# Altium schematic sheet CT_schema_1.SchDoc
size 327 x 469 mm
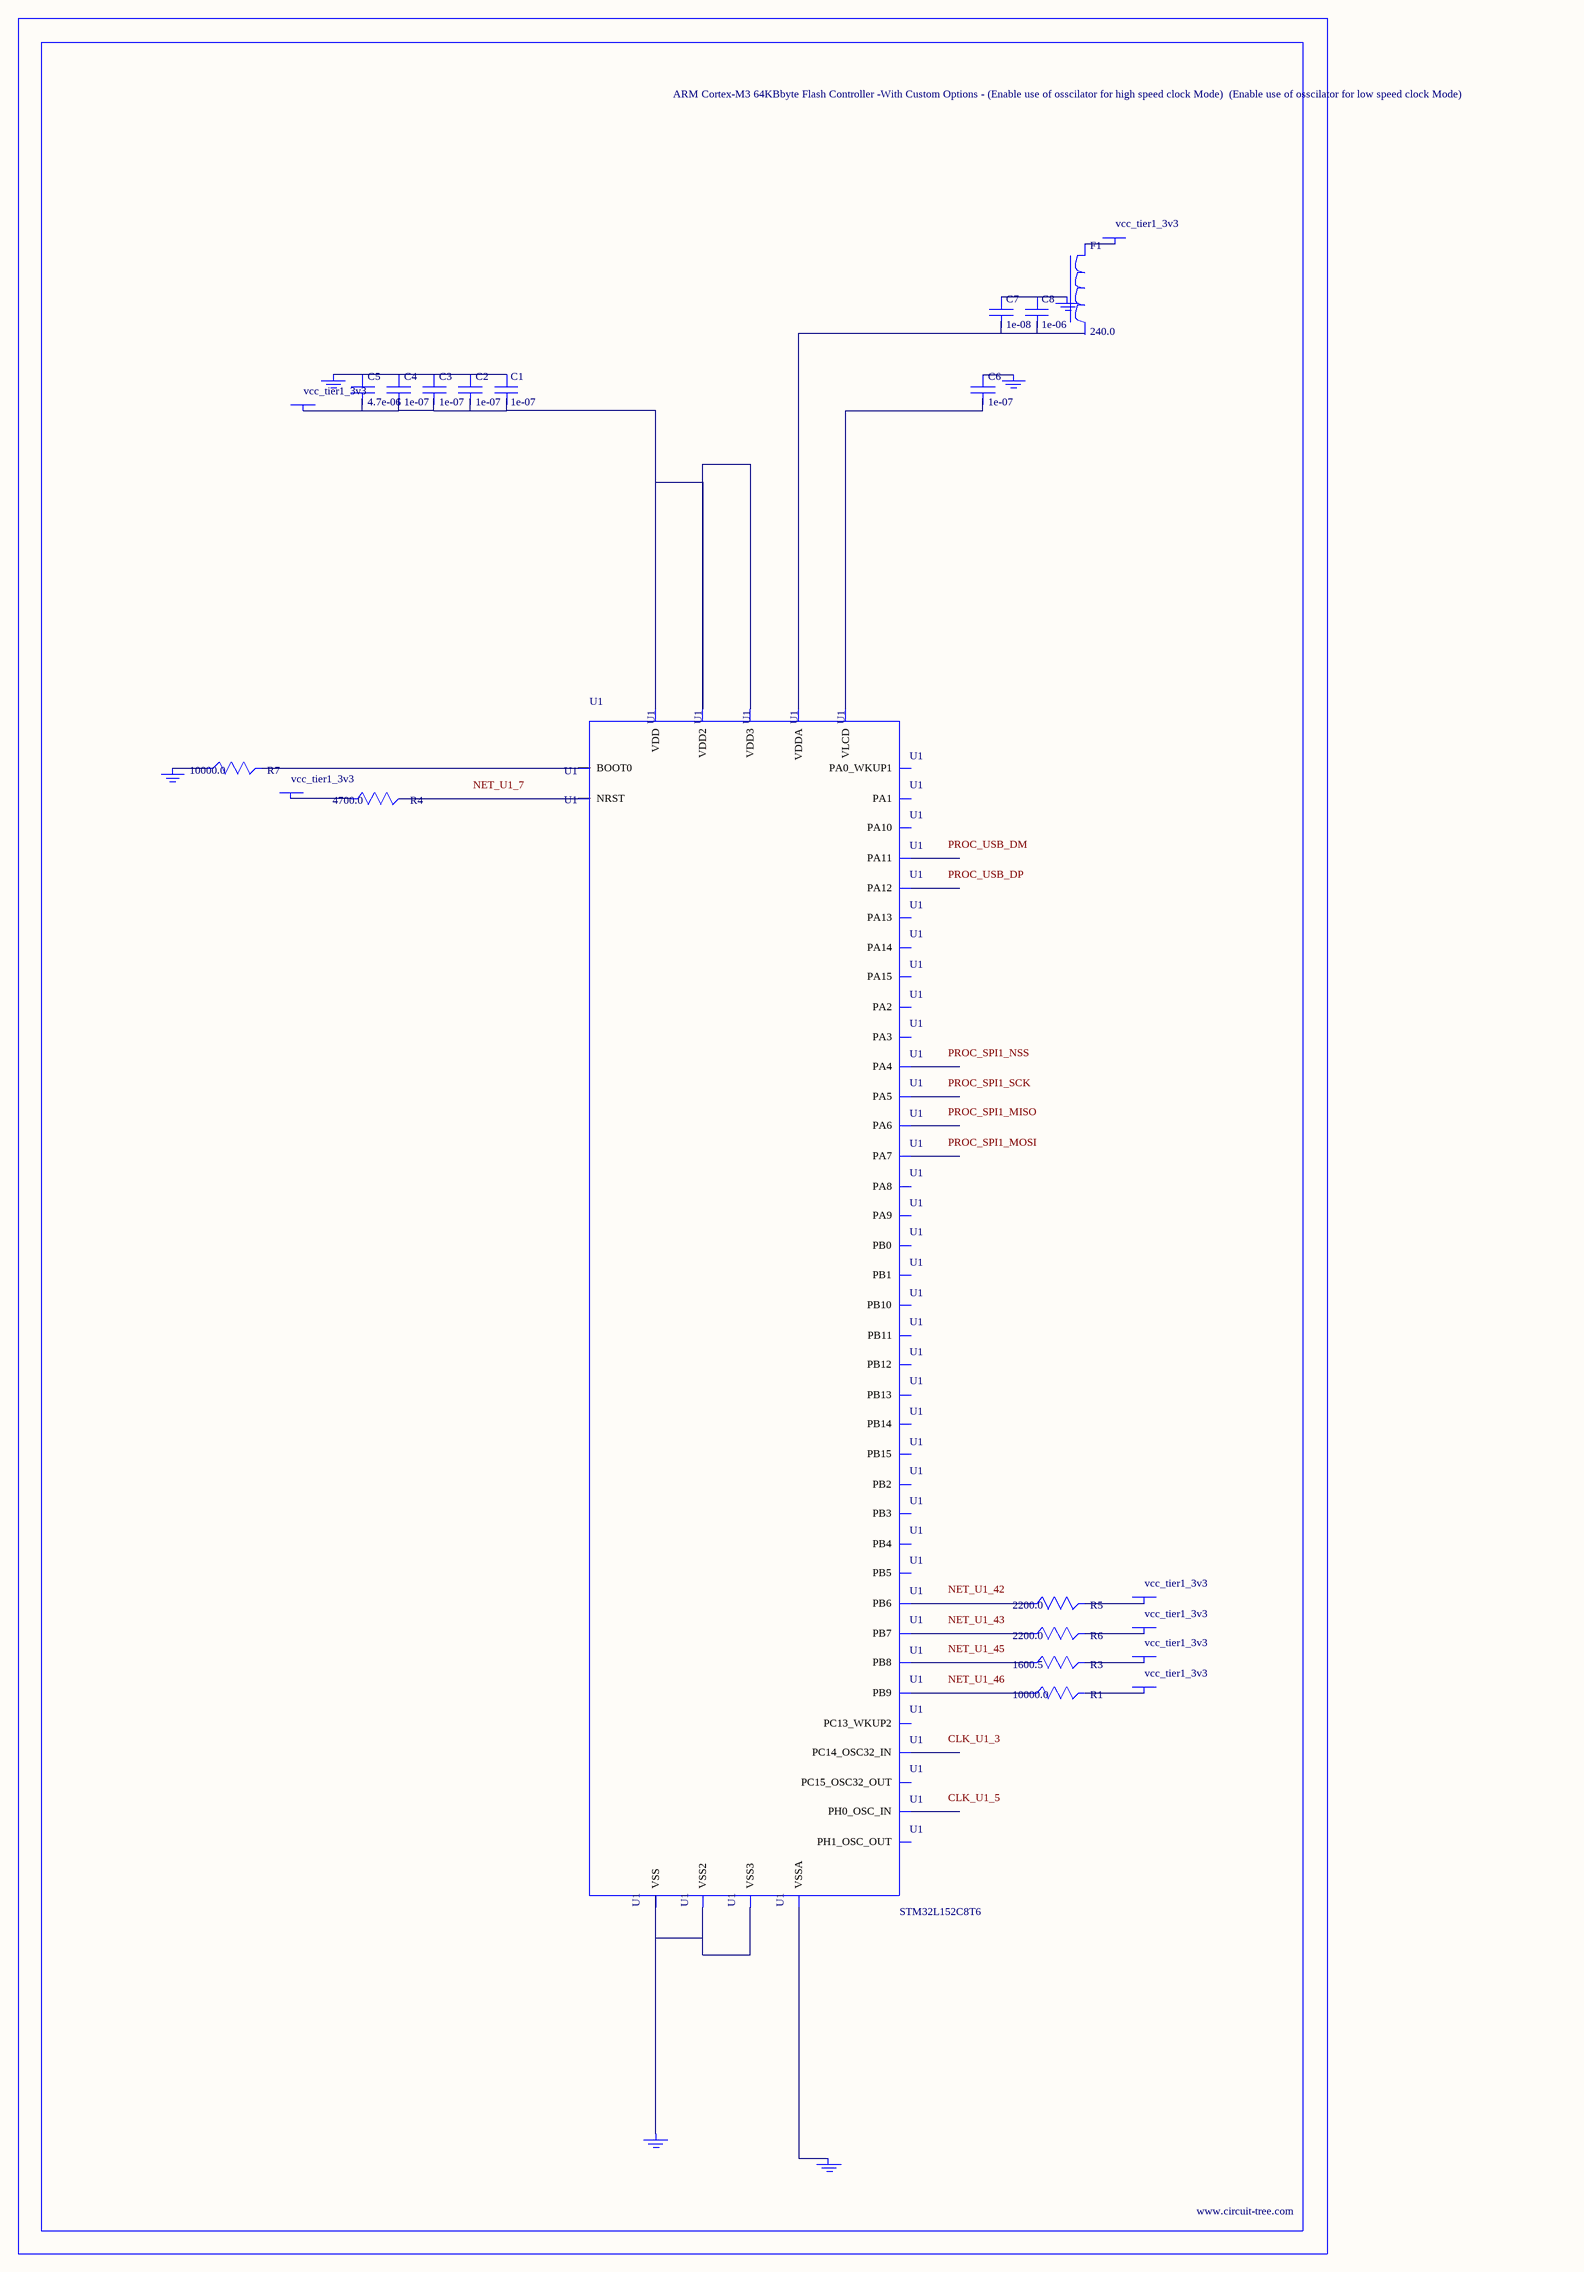
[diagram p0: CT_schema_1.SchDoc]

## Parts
BORDER0  (no value)
C1  1e-07  [C0603]
C2  1e-07  [C0603]
C3  1e-07  [C0603]
C4  1e-07  [C0603]
C5  4.7e-06  [C0603]
C6  1e-07  [C0603]
C7  1e-08  [C0603]
C8  1e-06  [C0603]
F1  240.0  [L0603]
GND_INSTANCE_0_0  (no value)
GND_INSTANCE_0_1  (no value)
GND_INSTANCE_0_2  (no value)
GND_INSTANCE_0_3  (no value)
GND_INSTANCE_0_4  (no value)
GND_INSTANCE_0_5  (no value)
POWER_INSTANCE_0_0  vcc_tier1_3v3
POWER_INSTANCE_0_1  vcc_tier1_3v3
POWER_INSTANCE_0_2  vcc_tier1_3v3
POWER_INSTANCE_0_3  vcc_tier1_3v3
POWER_INSTANCE_0_4  vcc_tier1_3v3
POWER_INSTANCE_0_5  vcc_tier1_3v3
POWER_INSTANCE_0_6  vcc_tier1_3v3
R1  10000.0  [R0603]
R3  1600.5  [R0603]
R4  4700.0  [R0603]
R5  2200.0  [R0603]
R6  2200.0  [R0603]
R7  10000.0  [R0603]
U1  STM32L152C8T6  [LQFP48]

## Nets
NetC1_1: C1.1 C2.1 C3.1 C4.1 C5.1 GND_INSTANCE_0_3.0(GND)
NetC1_2: C1.2 C2.2 C3.2 C4.2 C5.2 POWER_INSTANCE_0_1.0(PWR) U1.24(VDD) U1.36(VDD2) U1.48(VDD3)
NetC6_1: C6.1 GND_INSTANCE_0_0.0(GND)
NetC6_2: C6.2 U1.1(VLCD)
NetC7_1: C7.1 C8.1 GND_INSTANCE_0_2.0(GND)
NetC7_2: C7.2 C8.2 U1.9(VDDA)
NetF1_1: F1.1 POWER_INSTANCE_0_0.0(PWR)
NetGND_INSTANCE_0_1_0: GND_INSTANCE_0_1.0(GND) U1.8(VSSA)
NetGND_INSTANCE_0_4_0: GND_INSTANCE_0_4.0(GND) R7.1
NetGND_INSTANCE_0_5_0: GND_INSTANCE_0_5.0(GND) U1.23(VSS) U1.35(VSS2) U1.47(VSS3)
NetPOWER_INSTANCE_0_2_0: POWER_INSTANCE_0_2.0(PWR) R4.1
NetPOWER_INSTANCE_0_3_0: POWER_INSTANCE_0_3.0(PWR) R5.2
NetPOWER_INSTANCE_0_4_0: POWER_INSTANCE_0_4.0(PWR) R6.2
NetPOWER_INSTANCE_0_5_0: POWER_INSTANCE_0_5.0(PWR) R3.2
NetPOWER_INSTANCE_0_6_0: POWER_INSTANCE_0_6.0(PWR) R1.2
NetR1_1: R1.1 U1.46(PB9)
NetR3_1: R3.1 U1.45(PB8)
NetR4_2: R4.2 U1.7(NRST)
NetR5_1: R5.1 U1.42(PB6)
NetR6_1: R6.1 U1.43(PB7)
NetR7_2: R7.2 U1.44(BOOT0)

Not connected (* = marked no-connect by the designer): F1 2; U1 2(PC13_WKUP2) 3(PC14_OSC32_IN) 4(PC15_OSC32_OUT) 5(PH0_OSC_IN) 6(PH1_OSC_OUT) 10(PA0_WKUP1) 11(PA1) 12(PA2) 13(PA3) 14(PA4) 15(PA5) 16(PA6) 17(PA7) 18(PB0) 19(PB1) 20(PB2) 21(PB10) 22(PB11) 25(PB12) 26(PB13) 27(PB14) 28(PB15) 29(PA8) 30(PA9) 31(PA10) 32(PA11) 33(PA12) 34(PA13) 37(PA14) 38(PA15) 39(PB3) 40(PB4) 41(PB5)

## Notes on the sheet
- Labels drawn without touching a wire or pin: CLK_U1_3, CLK_U1_5, NET_U1_7, NET_U1_42, NET_U1_43, NET_U1_45, NET_U1_46, PROC_SPI1_MISO, PROC_SPI1_MOSI, PROC_SPI1_NSS, PROC_SPI1_SCK, PROC_USB_DM, PROC_USB_DP

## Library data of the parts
BORDER0 = BORDER_PAGE0
C1-C4 C6 = 06035C104K4Z2A
C5 = GRM188R6YA475KE15D
C7 = 06035C103K4Z2A
C8 = C0603C105K3RACTU
F1 = Z0603C241ASMST
GND_INSTANCE_0_0-GND_INSTANCE_0_5 = GND
POWER_INSTANCE_0_0-POWER_INSTANCE_0_6 = PWR
R1 R7 = RC0603JR-0710KL
R3 = R3
R4 = RC0603JR-074K7L
R5 R6 = RC0603JR-072K2L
